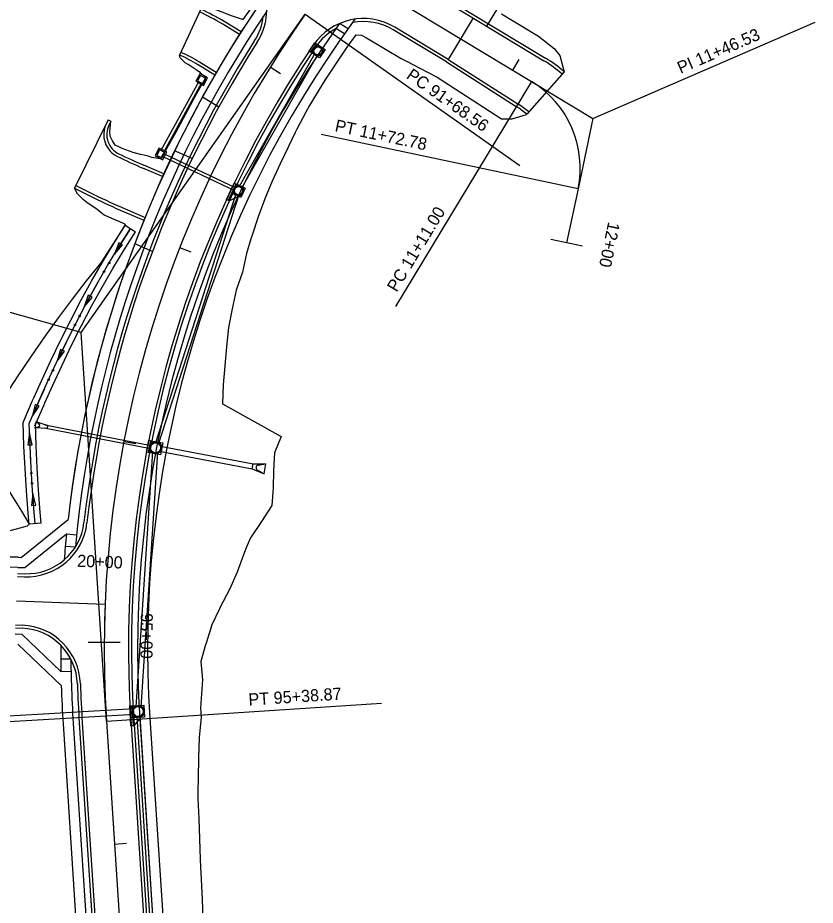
# Model space of a CAD drawing. Extents: x 979959 to 994833, y 1835619 to 1845316.
# Drawn here: x 982578.7 to 982973.5, y 1843025.1 to 1843464.2 of the extents above; entities that cross this region are included whole.
import ezdxf

# ---------------------------------------------------------------- set-up
doc = ezdxf.new("R2010")
doc.units = 0
for name, color, linetype in [('R_Drainage', 7, 'Continuous'), ('R_Horz Alg', 7, 'Continuous'), ('R_Horz Alg Annot', 7, 'Continuous'), ('R_Horz Alg Annot_Side Road', 7, 'Continuous'), ('R_Horz Alg Stationing', 7, 'Continuous'), ('R_Horz Alg Stationing_Side Road', 7, 'Continuous'), ('R_Proposed Const Limits', 7, 'Continuous'), ('R_Proposed Road', 7, 'Continuous'), ('R_Special Ditch', 7, 'Continuous')]:
    doc.layers.add(name, color=color, linetype=linetype)

msp = doc.modelspace()

# ---------------------------------------------------------------- linework, layer by layer
at = {"layer": 'R_Drainage'}
for p, q in [((982725.77, 1843446.61), (982688.24, 1843380.66)), ((982727.07, 1843445.87), (982689.55, 1843379.92)), ((982730.81, 1843448.53), (982728.02, 1843444.38)), ((982668.38, 1843432.68), (982649.61, 1843398.51)), ((982669.68, 1843431.95), (982650.97, 1843397.86)), ((982650.6, 1843395.55), (982685.98, 1843378.79)), ((982651.24, 1843396.9), (982686.62, 1843380.15)), ((982686.79, 1843382.01), (982682.94, 1843373.87)), ((982686.69, 1843377.14), (982646.96, 1843253.97)), ((982688.12, 1843376.68), (982648.39, 1843253.51)), ((982683.39, 1843373.66), (982689.07, 1843376.43)), ((982691.31, 1843379.87), (982689.17, 1843375.35)), ((982587.67, 1843264.35), (982587.1, 1843261.41)), ((982588.76, 1843261.65), (982587.1, 1843261.41)), ((982593.21, 1843261), (982587.1, 1843261.41)), ((982593.5, 1843262.47), (982587.67, 1843264.35)), ((982589.11, 1843263.51), (982587.67, 1843264.35)), ((982592.08, 1843262.74), (982644.74, 1843252.65)), ((982593.5, 1843262.47), (982593.21, 1843261)), ((982591.8, 1843261.27), (982644.46, 1843251.18)), ((982637.27, 1843123.27), (982645.55, 1843249.39)), ((982639.76, 1843123.11), (982648.05, 1843249.23)), ((982648.83, 1843249.83), (982694.83, 1843241.02)), ((982649.3, 1843252.29), (982695.3, 1843243.48)), ((982694.83, 1843241.02), (982695.3, 1843243.48)), ((982694.83, 1843241.02), (982700.63, 1843238.64)), ((982695.3, 1843243.48), (982701.58, 1843243.55)), ((982697.27, 1843240.62), (982700.63, 1843238.64)), ((982697.71, 1843242.93), (982701.58, 1843243.55)), ((982700.63, 1843238.64), (982701.58, 1843243.55)), ((982567.9, 1843118.44), (982636.29, 1843122.41)), ((982635.21, 1843123.86), (982635.77, 1843113.88)), ((982636.46, 1843119.42), (982568.08, 1843115.44)), ((982636.26, 1843113.9), (982640.66, 1843119.09)), ((982651.28, 1842908.52), (982637.78, 1843118.6)), ((982652.77, 1842908.62), (982639.27, 1843118.7))]:
    msp.add_line(p, q, dxfattribs=at)
for points in [[(982727.08, 1843451.04), (982724.28, 1843446.9), (982723.04, 1843447.73), (982725.83, 1843451.88)], [(982730.81, 1843448.53), (982728.02, 1843444.38), (982723.87, 1843447.18), (982726.66, 1843451.32)], [(982668.95, 1843436.57), (982666.82, 1843432.8), (982670.59, 1843430.67), (982672.72, 1843434.44)], [(982669.2, 1843435.66), (982667.73, 1843433.05), (982670.34, 1843431.58), (982671.81, 1843434.19)], [(982648.53, 1843399.75), (982646.68, 1843395.84), (982650.59, 1843393.98), (982652.45, 1843397.9)], [(982648.85, 1843398.86), (982647.57, 1843396.15), (982650.28, 1843394.87), (982651.56, 1843397.58)], [(982687.24, 1843381.79), (982683.39, 1843373.66), (982682.03, 1843374.3), (982685.88, 1843382.44)], [(982691.31, 1843379.87), (982689.17, 1843375.35), (982684.65, 1843377.49), (982686.79, 1843382.01)], [(982645.05, 1843254.89), (982643.92, 1843248.99), (982642.45, 1843249.28), (982643.58, 1843255.17)], [(982650.45, 1843253.85), (982649.32, 1843247.96), (982643.43, 1843249.09), (982644.56, 1843254.98)], [(982635.71, 1843123.89), (982636.26, 1843113.9), (982634.77, 1843113.82), (982634.21, 1843123.81)], [(982641.2, 1843124.19), (982641.53, 1843118.2), (982635.54, 1843117.87), (982635.21, 1843123.86)]]:
    msp.add_lwpolyline(points, close=True, dxfattribs=at)
for centre, radius in [((982727.34, 1843447.85), 2.5), ((982727.34, 1843447.85), 2.5), ((982727.34, 1843447.85), 2), ((982727.34, 1843447.85), 2), ((982687.98, 1843378.68), 2.5), ((982687.98, 1843378.68), 2.5), ((982687.98, 1843378.68), 2), ((982687.98, 1843378.68), 2), ((982646.94, 1843251.47), 3), ((982646.94, 1843251.47), 3), ((982646.94, 1843251.47), 2.5), ((982646.94, 1843251.47), 2.5), ((982638.37, 1843121.03), 3), ((982638.37, 1843121.03), 3), ((982638.37, 1843121.03), 2.5), ((982638.37, 1843121.03), 2.5)]:
    msp.add_circle(centre, radius, dxfattribs=at)
for centre, radius, start, end in [((982588.61, 1843262.64), 1, 278.5105, 59.7965), ((982697.91, 1843241.7), 1.25, 98.9714, 239.3331)]:
    msp.add_arc(centre, radius, start, end, dxfattribs=at)
at = {"layer": 'R_Horz Alg'}
for p, q in [((982737.99, 1843490.1), (982832.99, 1843432.69)), ((982856.04, 1843379.55), (982850.41, 1843352.92)), ((982578.07, 1843175.81), (982621.93, 1843174.03)), ((982622.64, 1843116.25), (982652.68, 1842656.1))]:
    msp.add_line(p, q, dxfattribs=at)
for centre, radius, start, end in [((983167.15, 1843151.8), 545.67, 144.8526, 183.7353), ((982807.13, 1843389.9), 50, 348.0569, 58.8526)]:
    msp.add_arc(centre, radius, start, end, dxfattribs=at)
at = {"layer": 'R_Horz Alg Annot'}
for p, q in [((982610.09, 1843308.44), (982720.97, 1843465.93)), ((982832.99, 1843432.69), (982863.4, 1843414.31)), ((982863.4, 1843414.31), (982856.04, 1843379.55)), ((982622.64, 1843116.25), (982610.09, 1843308.44))]:
    msp.add_line(p, q, dxfattribs=at)
for points in [[(982720.97, 1843465.93), (982827.27, 1843391.09)], [(982610.09, 1843308.44), (982494.57, 1843340.93)], [(982622.64, 1843116.25), (982758.78, 1843125.13)]]:
    msp.add_lwpolyline(points, dxfattribs=at)
at = {"layer": 'R_Horz Alg Annot_Side Road'}
for points in [[(982863.4, 1843414.31), (982973.48, 1843462.07)], [(982832.99, 1843432.69), (982765.75, 1843321.43)], [(982856.04, 1843379.55), (982728.86, 1843406.45)]]:
    msp.add_lwpolyline(points, dxfattribs=at)
at = {"layer": 'R_Horz Alg Stationing'}
for points in [[(982708.72, 1843436.55), (982703.62, 1843439.72)], [(982664.5, 1843348.24), (982658.91, 1843350.43)], [(982637.12, 1843253.35), (982631.23, 1843254.48)], [(982622.26, 1843182.02), (982621.6, 1843166.03)], [(982629.49, 1843155.05), (982613.49, 1843155.14)], [(982632.61, 1843055.64), (982626.62, 1843055.25)]]:
    msp.add_lwpolyline(points, dxfattribs=at)
at = {"layer": 'R_Horz Alg Stationing_Side Road'}
for points in [[(982826.67, 1843443.51), (982823.57, 1843438.38)], [(982858.24, 1843351.27), (982842.58, 1843354.58)]]:
    msp.add_lwpolyline(points, dxfattribs=at)
at = {"layer": 'R_Proposed Const Limits'}
for points in [[(982690.14, 1843463.32), (982689.91, 1843463.41), (982687.97, 1843464.06), (982685.97, 1843464.63), (982684.07, 1843465.35), (982682.06, 1843466.17), (982679.87, 1843467.02), (982677.69, 1843467.88), (982675.51, 1843468.7), (982673.42, 1843468.97), (982671.14, 1843469.02), (982669.27, 1843468.5)], [(982695.38, 1843470.9), (982694.68, 1843469.84), (982694.68, 1843469.84), (982690.14, 1843463.32)], [(982818.25, 1843466.21), (982823.68, 1843462.86), (982836.55, 1843455.18), (982844.3, 1843449.09), (982847, 1843445.5), (982849.17, 1843437.48)], [(982746.1, 1843455.76), (982741.68, 1843449.67), (982736.29, 1843441.83), (982736.29, 1843441.83), (982731.08, 1843433.86), (982726.08, 1843425.77), (982723.68, 1843421.67), (982723.17, 1843420.79), (982721.33, 1843417.52), (982716.88, 1843409.11), (982716.04, 1843407.4), (982712.73, 1843400.55), (982708.6, 1843392), (982704.68, 1843383.35), (982701, 1843374.61), (982700.3, 1843372.84), (982697.64, 1843365.73), (982694.74, 1843356.68), (982694.16, 1843354.88), (982691.9, 1843347.65), (982689.91, 1843338.31), (982686.82, 1843329.44), (982684.81, 1843320.2), (982683.05, 1843310.93), (982682.01, 1843301.48), (982681.14, 1843292.04), (982680.37, 1843282.65), (982680.06, 1843273.21), (982709.08, 1843257.1), (982705.73, 1843249), (982705.26, 1843240.29), (982705.13, 1843231.57), (982704.49, 1843222.98), (982699.44, 1843215), (982693.94, 1843206.94), (982692.17, 1843202.74), (982690.64, 1843199.07), (982690.42, 1843198.51), (982687.34, 1843189.95), (982683.47, 1843181.35), (982678.99, 1843172.65), (982678.56, 1843171.72), (982674.84, 1843163.8), (982671.92, 1843154.79), (982671.53, 1843153.55), (982669.3, 1843145.68), (982670.12, 1843136.58), (982669.46, 1843127.42), (982669.22, 1843122.84), (982669.48, 1843118.18), (982668.53, 1843108.09), (982668.11, 1843098.04), (982667.94, 1843088.01), (982667.86, 1843081.62), (982667.92, 1843077.99), (982668.4, 1843068), (982668.7, 1843058), (982669.02, 1843048), (982669.22, 1843044.13), (982669.53, 1843038.01), (982670.04, 1843028.02), (982670.41, 1843018.02)], [(982746.1, 1843455.76), (982741.68, 1843449.67), (982736.29, 1843441.83), (982736.29, 1843441.83), (982731.08, 1843433.86), (982726.08, 1843425.77), (982723.68, 1843421.67), (982723.17, 1843420.79), (982721.33, 1843417.52), (982716.88, 1843409.11), (982716.04, 1843407.4), (982712.73, 1843400.55), (982708.6, 1843392), (982704.68, 1843383.35), (982701, 1843374.61), (982700.3, 1843372.84), (982697.64, 1843365.73), (982694.74, 1843356.68), (982694.16, 1843354.88), (982691.9, 1843347.65), (982689.91, 1843338.31), (982686.82, 1843329.44), (982684.81, 1843320.2), (982683.05, 1843310.93), (982682.01, 1843301.48), (982681.14, 1843292.04), (982680.37, 1843282.65), (982680.06, 1843273.21), (982709.08, 1843257.1), (982705.73, 1843249), (982705.26, 1843240.29), (982705.13, 1843231.57), (982704.49, 1843222.98), (982699.44, 1843215), (982693.94, 1843206.94), (982692.17, 1843202.74), (982690.64, 1843199.07), (982690.42, 1843198.51), (982687.34, 1843189.95), (982683.47, 1843181.35), (982678.99, 1843172.65), (982678.56, 1843171.72), (982674.84, 1843163.8), (982671.92, 1843154.79), (982671.53, 1843153.55), (982669.3, 1843145.68), (982670.12, 1843136.58), (982669.46, 1843127.42), (982669.22, 1843122.84), (982669.48, 1843118.18), (982668.53, 1843108.09), (982668.11, 1843098.04), (982667.94, 1843088.01), (982667.86, 1843081.62), (982667.92, 1843077.99), (982668.4, 1843068), (982668.7, 1843058), (982669.02, 1843048), (982669.22, 1843044.13), (982669.53, 1843038.01), (982670.04, 1843028.02), (982670.41, 1843018.02)], [(982746.1, 1843455.76), (982748.81, 1843455.64), (982751.38, 1843454.37), (982759.94, 1843449.19), (982768.52, 1843444.05), (982771.19, 1843442.67), (982774.65, 1843440.87), (982777.43, 1843439.46), (982786.3, 1843434.8), (982818.1, 1843414.17), (982823.52, 1843414.17), (982830.53, 1843416.43)], [(982671.8, 1843434.8), (982670.73, 1843435.73), (982669.2, 1843437.05), (982667.56, 1843438.21), (982665.97, 1843439.19), (982664.57, 1843440.17), (982663.13, 1843441.08), (982661.66, 1843441.94), (982660.47, 1843443.11), (982659.19, 1843444.47), (982658.86, 1843445.77)], [(982671.8, 1843434.8), (982670.8, 1843433.04), (982666.73, 1843425.73), (982661.68, 1843416.58), (982656.75, 1843407.35), (982651.65, 1843398.19), (982650.44, 1843396.45), (982649.38, 1843394.4)], [(982649.38, 1843394.4), (982649.19, 1843394.43), (982647.13, 1843394.69), (982645.15, 1843395.16), (982643.21, 1843395.71), (982641.36, 1843396.2), (982639.49, 1843396.64), (982637.62, 1843397.09), (982635.77, 1843397.58), (982633.97, 1843398.21), (982632.17, 1843398.82), (982630.44, 1843399.6), (982628.71, 1843400.39), (982626.89, 1843401.2), (982625.59, 1843403.35), (982624.47, 1843405.6), (982624.32, 1843408.03), (982624.57, 1843411.11), (982624.85, 1843413.01)], [(982632.01, 1843362.02), (982631.1, 1843362.44), (982629.25, 1843363.2), (982627.3, 1843364.02), (982625.36, 1843364.87), (982623.42, 1843365.72), (982621.5, 1843366.62), (982619.78, 1843367.95), (982618.07, 1843369.29), (982616.3, 1843370.48), (982614.54, 1843371.67), (982612.85, 1843372.8), (982611.32, 1843374.21), (982609.78, 1843375.62), (982608.25, 1843377.03), (982606.8, 1843379.88)], [(982632.01, 1843362.02), (982619.81, 1843342.9), (982612.66, 1843334.07), (982605.62, 1843325.04), (982598.73, 1843315.83), (982591.98, 1843306.41), (982585.33, 1843296.82), (982578.75, 1843287.06), (982572.25, 1843277.12), (982565.85, 1843267.01), (982567.92, 1843255.26), (982570.41, 1843243.61), (982573.2, 1843232.06), (982580.65, 1843220.14), (982584.41, 1843213.7)], [(982502.72, 1843189.18), (982502.91, 1843189.28), (982513.91, 1843193.62), (982525.01, 1843197.84), (982536.51, 1843200.87), (982548.21, 1843203.1), (982559.92, 1843206.46), (982571.97, 1843209.66), (982583.48, 1843212.83), (982584.41, 1843213.7)]]:
    msp.add_lwpolyline(points, dxfattribs=at)
at = {"layer": 'R_Proposed Road'}
for p, q in [((982782.74, 1843477.08), (982839.19, 1843442.96)), ((982783.52, 1843478.36), (982839.97, 1843444.24)), ((982669.27, 1843468.5), (982658.86, 1843445.77)), ((982810.95, 1843460.03), (982815.86, 1843468.16)), ((982745.58, 1843463.55), (982738.55, 1843453.55)), ((982688.45, 1843455.98), (982680.16, 1843461.03)), ((982689.25, 1843457.25), (982680.94, 1843462.31)), ((982737.95, 1843461.39), (982734.46, 1843456.43)), ((982742.22, 1843458.78), (982737.95, 1843461.39)), ((982791.69, 1843443.63), (982765.38, 1843459.53)), ((982740.48, 1843456.31), (982736.2, 1843458.91)), ((982790.91, 1843442.34), (982764.6, 1843458.24)), ((982677.01, 1843437.19), (982668.72, 1843442.23)), ((982790.88, 1843442.36), (982825.46, 1843420.3)), ((982791.69, 1843443.63), (982826.26, 1843421.56)), ((982676.26, 1843435.89), (982667.94, 1843440.95)), ((982849.17, 1843437.48), (982830.63, 1843416.5)), ((982678.24, 1843420.05), (982670.11, 1843425)), ((982623.5, 1843413.67), (982606.8, 1843379.88)), ((982623.5, 1843413.67), (982624.85, 1843413.01)), ((982624.85, 1843413.01), (982623.88, 1843411.05)), ((982665.09, 1843394.57), (982656.36, 1843398.32)), ((982650.42, 1843385.63), (982640.59, 1843389.85)), ((982651.04, 1843387), (982641.18, 1843391.23)), ((982607.46, 1843381.23), (982616.78, 1843376.62)), ((982606.8, 1843379.88), (982616.11, 1843375.28)), ((982631.32, 1843368.26), (982641.18, 1843364.03)), ((982631.91, 1843369.64), (982641.74, 1843365.42)), ((982645.37, 1843348.62), (982636.63, 1843352.38)), ((982580.46, 1843197.24), (982603.61, 1843215.91)), ((982582.14, 1843192.16), (982602.86, 1843208.88)), ((982602.86, 1843208.88), (982607.83, 1843208.37)), ((982602.28, 1843202.85), (982607.26, 1843202.4)), ((982578.95, 1843197.3), (982580.46, 1843197.24)), ((982578.75, 1843192.3), (982582.14, 1843192.16)), ((982578.56, 1843187.8), (982581.96, 1843187.67)), ((982578.62, 1843189.3), (982582.02, 1843189.17)), ((982577.52, 1843162.33), (982580.92, 1843162.19)), ((982577.58, 1843163.82), (982580.98, 1843163.69)), ((982577.4, 1843159.33), (982580.79, 1843159.19)), ((982600.08, 1843140.85), (982580.79, 1843159.19)), ((982600.26, 1843133.77), (982578.71, 1843154.27)), ((982605, 1843146.94), (982600, 1843146.9)), ((982600.08, 1843140.85), (982605.08, 1843140.94)), ((982634.61, 1843117.03), (982648.04, 1842911.34)), ((982636.11, 1843117.13), (982649.53, 1842911.48)), ((982639.1, 1843117.32), (982652.52, 1842911.77)), ((982644.09, 1843117.65), (982657.5, 1842912.24)), ((982601.18, 1843114.85), (982614.59, 1842909.44)), ((982606.17, 1843115.17), (982619.59, 1842909.62)), ((982609.17, 1843115.37), (982622.59, 1842909.72)), ((982610.66, 1843115.46), (982624.09, 1842909.78))]:
    msp.add_line(p, q, dxfattribs=at)
msp.add_lwpolyline([(982804.1, 1843464.17), (982791.69, 1843443.63)], dxfattribs=at)
for centre, radius, start, end in [((982671.97, 1843468.27), 30, 327.4171, 67.8526), ((983167.15, 1843151.8), 567.17, 145.2433, 173.5095), ((983167.15, 1843151.8), 567.17, 145.8418, 173.5095), ((982622.45, 1843366.2), 112.5, 58.6781, 65.4099), ((983167.15, 1843151.8), 562.17, 145.8418, 174.8356), ((982622.45, 1843366.2), 111, 58.6781, 65.4099), ((982671.97, 1843468.27), 28.5, 327.4171, 353.3151), ((982749.86, 1843433.85), 30, 58.8526, 145.9443), ((982749.86, 1843433.85), 28.5, 58.8526, 101.1144), ((983167.15, 1843151.8), 529.17, 144.8526, 183.7353), ((982749.86, 1843433.85), 28.5, 118.7418, 145.9443), ((983167.15, 1843151.8), 559.17, 147.4171, 173.5668), ((983167.15, 1843151.8), 557.67, 147.4171, 173.5668), ((983167.15, 1843151.8), 533.67, 145.9443, 183.7353), ((983167.15, 1843151.8), 524.17, 144.8526, 183.7353), ((983167.15, 1843151.8), 532.17, 145.9443, 183.7353), ((982622.45, 1843366.2), 89, 58.6781, 65.4099), ((982622.45, 1843366.2), 87.5, 58.6781, 65.4099), ((982807.13, 1843389.9), 62, 48.5394, 58.8526), ((982807.13, 1843389.9), 63.5, 48.5394, 58.8526), ((982807.13, 1843389.9), 35.5, 48.5394, 58.8526), ((982807.13, 1843389.9), 37, 48.5394, 58.8526), ((982633.29, 1843406.39), 12, 153.6922, 244.0244), ((982633.29, 1843406.39), 10.5, 153.6922, 244.0244), ((982754.61, 1843655.41), 289, 244.0244, 246.763), ((982754.61, 1843655.41), 287.5, 244.0244, 246.763), ((982754.61, 1843655.41), 311, 243.6922, 246.763), ((982754.61, 1843655.41), 312.5, 243.6922, 246.763), ((982583.18, 1843217.64), 30, 267.6651, 353.5668), ((982583.18, 1843217.64), 28.5, 267.6651, 353.5668), ((983167.15, 1843151.8), 567.17, 174.2241, 175.5318), ((982571.96, 1843025.94), 171.5, 87.6651, 135.8342), ((982571.96, 1843025.94), 166.5, 87.6651, 136.9251), ((982579.76, 1843133.71), 28.5, 1.7635, 87.6651), ((982579.76, 1843133.71), 30, 1.7635, 87.6651), ((983167.15, 1843151.8), 567.17, 179.7985, 181.1062), ((983167.15, 1843151.8), 562.17, 180.4947, 181.7635), ((983167.15, 1843151.8), 562.17, 181.7635, 183.7353), ((983167.15, 1843151.8), 559.17, 181.7635, 183.7353), ((983167.15, 1843151.8), 557.67, 181.7635, 183.7353), ((983167.15, 1843151.8), 567.17, 181.8208, 183.7353)]:
    msp.add_arc(centre, radius, start, end, dxfattribs=at)
at = {"layer": 'R_Special Ditch'}
for p, q in [((982631.95, 1843361.57), (982637.02, 1843358.37)), ((982628.74, 1843352.93), (982626.55, 1843347.24)), ((982626.55, 1843347.24), (982630.56, 1843351.83)), ((982630.56, 1843351.83), (982628.74, 1843352.93)), ((982613.63, 1843326.92), (982611.67, 1843321.16)), ((982611.67, 1843321.16), (982615.48, 1843325.9)), ((982615.48, 1843325.9), (982613.63, 1843326.92)), ((982599.89, 1843300.16), (982598.23, 1843294.29)), ((982598.23, 1843294.29), (982601.79, 1843299.23)), ((982601.79, 1843299.23), (982599.89, 1843300.16)), ((982587.3, 1843272.83), (982585.91, 1843266.9)), ((982585.91, 1843266.9), (982589.25, 1843272)), ((982589.25, 1843272), (982587.3, 1843272.83)), ((982584.58, 1843258.92), (982583.72, 1843252.88)), ((982585.84, 1843252.96), (982584.58, 1843258.92)), ((982583.72, 1843252.88), (982585.84, 1843252.96)), ((982586.15, 1843228.92), (982585.57, 1843222.86)), ((982587.68, 1843223.02), (982586.15, 1843228.92)), ((982585.57, 1843222.86), (982587.68, 1843223.02)), ((982590.38, 1843214.24), (982584.41, 1843213.7))]:
    msp.add_line(p, q, dxfattribs=at)
for points in [[(982581.41, 1843264.01), (982586.05, 1843274.84), (982586.61, 1843276.1), (982590.57, 1843284.96), (982595.22, 1843294.97), (982600, 1843304.86), (982604.91, 1843314.64), (982609.97, 1843324.3), (982615.21, 1843333.84), (982620.63, 1843343.23), (982626.21, 1843352.49), (982631.95, 1843361.57)], [(982584.43, 1843263.45), (982588.8, 1843273.64), (982589.35, 1843274.87), (982593.3, 1843283.72), (982597.93, 1843293.68), (982602.69, 1843303.53), (982607.58, 1843313.27), (982612.62, 1843322.89), (982617.83, 1843332.37), (982623.21, 1843341.71), (982628.77, 1843350.91), (982634.48, 1843359.97)], [(982587.18, 1843262.26), (982591.55, 1843272.43), (982592.09, 1843273.65), (982596.03, 1843282.47), (982600.64, 1843292.4), (982605.39, 1843302.21), (982610.25, 1843311.9), (982615.26, 1843321.47), (982620.44, 1843330.9), (982625.8, 1843340.19), (982631.32, 1843349.34), (982637.02, 1843358.37)], [(982634.48, 1843359.97), (982628.77, 1843350.91), (982626.55, 1843347.24)], [(982618.93, 1843334.28), (982617.83, 1843332.37), (982612.62, 1843322.89), (982611.7, 1843321.14)], [(982618.95, 1843334.31), (982618.93, 1843334.28)], [(982604.82, 1843307.77), (982602.69, 1843303.53), (982598.23, 1843294.29)], [(982604.84, 1843307.8), (982604.82, 1843307.77)], [(982591.93, 1843280.64), (982589.35, 1843274.87), (982588.8, 1843273.64), (982585.91, 1843266.9)], [(982591.94, 1843280.67), (982591.93, 1843280.64)], [(982584.41, 1843213.7), (982583.91, 1843219.16), (982583.05, 1843230.12), (982582.34, 1843241.14), (982581.8, 1843252.23), (982581.41, 1843264.01)], [(982587.39, 1843213.97), (982586.9, 1843219.41), (982586.04, 1843230.33), (982585.34, 1843241.31), (982584.8, 1843252.35), (982584.43, 1843263.45)], [(982590.38, 1843214.24), (982589.89, 1843219.66), (982589.03, 1843230.54), (982588.33, 1843241.48), (982587.8, 1843252.47), (982587.43, 1843263.55)], [(982585.21, 1843243.93), (982584.8, 1843252.35), (982584.58, 1843258.92)], [(982585.21, 1843243.89), (982585.21, 1843243.93)], [(982587.39, 1843213.97), (982586.9, 1843219.41), (982586.15, 1843228.92)]]:
    msp.add_lwpolyline(points, dxfattribs=at)
for centre in [(982624, 1843342.94), (982621.47, 1843338.61), (982609.41, 1843316.69), (982607.1, 1843312.24), (982596.14, 1843289.74), (982594.03, 1843285.2), (982585.46, 1843238.91), (982585.78, 1843233.91)]:
    msp.add_circle(centre, 0.375, dxfattribs=at)

# ---------------------------------------------------------------- texts
at = {"layer": 'R_Horz Alg Annot'}
for s, rotation, p in [('PC 91+68.56', 324.8526, (982770.63, 1843434.63)), ('PT 95+38.87', 3.7353, (982693.1, 1843123.89))]:
    msp.add_text(s, height=6, rotation=rotation, dxfattribs=at).set_placement(p)
at = {"layer": 'R_Horz Alg Annot_Side Road'}
for s, rotation, p in [('PI 11+46.53', 23.4548, (982906.81, 1843436.42)), ('PT 11+72.78', 348.0569, (982735.35, 1843408.14)), ('PC 11+11.00', 58.8526, (982766.28, 1843328.12))]:
    msp.add_text(s, height=6, rotation=rotation, dxfattribs=at).set_placement(p)
at = {"layer": 'R_Horz Alg Stationing'}
for s, rotation, p in [('20+00', 357.6651, (982608.03, 1843192.61)), ('95+00', 269.6535, (982639.58, 1843169.63))]:
    msp.add_text(s, height=6, rotation=rotation, dxfattribs=at).set_placement(p)
at = {"layer": 'R_Horz Alg Stationing_Side Road'}
msp.add_text('12+00', height=6, rotation=258.0569, dxfattribs=at).set_placement((982871.05, 1843363.53))

doc.saveas('drawing.dxf')
